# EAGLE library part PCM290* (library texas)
STEREO AUDIO CODEC WITH USB INTERFACE SINGLE-ENDED ANALOG INPUT/OUTPUT AND S/PDIF
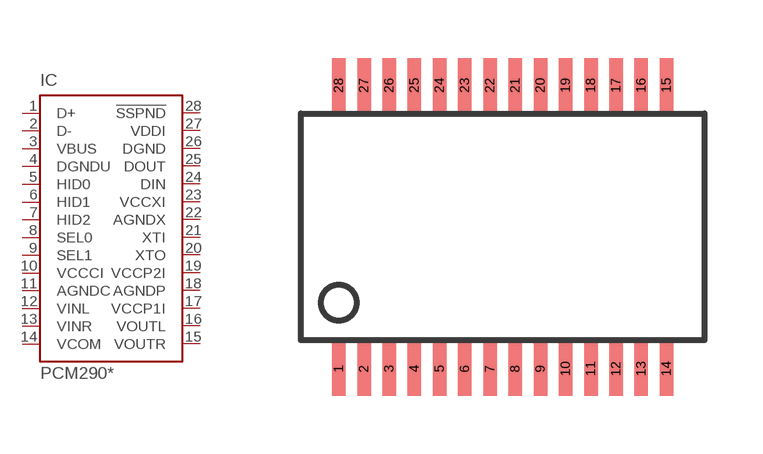
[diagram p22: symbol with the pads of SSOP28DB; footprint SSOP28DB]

Designator prefix IC

## PCM2902E (MF: TEXAS INSTRUMENT CONNECTORS; MPN: PCM2902E; OC_FARNELL: 1207089; OC_NEWARK: 75C5380), PCM2906DB (MF: TEXAS INSTRUMENT CONNECTORS; MPN: PCM2906DB; OC_FARNELL: unknown; OC_NEWARK: 83C7389)  [SSOP28DB]
1  D+
2  D-
3  VBUS  pwr
4  DGNDU  pwr
5  HID0  in
6  HID1  in
7  HID2  in
8  SEL0  in
9  SEL1  in
10  VCCCI  pwr
11  AGNDC  pwr
12  VINL  in
13  VINR  in
14  VCOM  pwr
15  VOUTR  out
16  VOUTL  out
17  VCCP1I  in
18  AGNDP  pwr
19  VCCP2I  pwr
20  XTO  out
21  XTI  in
22  AGNDX  pwr
23  VCCXI  pwr
24  DIN  in
25  DOUT  out
26  DGND  pwr
27  VDDI  pwr
28  !SSPND  out

## Footprint SSOP28DB (pad centres in mm)
Small Shrink Outline Package
smd 0.348 x 1.397: 1 -4.225,-3.656; 2 -3.575,-3.656; 3 -2.925,-3.656; 4 -2.275,-3.656; 5 -1.625,-3.656; 6 -0.975,-3.656; 7 -0.325,-3.656; 8 0.325,-3.656; 9 0.975,-3.656; 10 1.625,-3.656; 11 2.275,-3.656; 12 2.925,-3.656; 13 3.575,-3.656; 14 4.225,-3.656; 15 4.225,3.656; 16 3.575,3.656; 17 2.925,3.656; 18 2.275,3.656; 19 1.625,3.656; 20 0.975,3.656; 21 0.325,3.656; 22 -0.325,3.656; 23 -0.975,3.656; 24 -1.625,3.656; 25 -2.275,3.656; 26 -2.925,3.656; 27 -3.575,3.656; 28 -4.225,3.656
